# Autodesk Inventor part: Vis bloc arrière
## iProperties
Shininess: 20.0
Angle Display Precision: 2
Document Length Units: 11269
Document Angle Units: 11279
Document Time Units: 11290
Document Mass Units: 11283
Document Length Units Precision: 3
Document Angle Units Precision: 2
Compacted: True
Created: 2002-09
Part Number: Vis bloc arrière
Material: Par défaut
Document SubType Name: Modélisation
Designer: administrateur
Density: 0.0
Volumn: 0.0
Area: 0.0
PropertySet Name: Model Information
Control State: 0
Master: False
Checked Out: False
Author: administrateur
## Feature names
1. Base1
